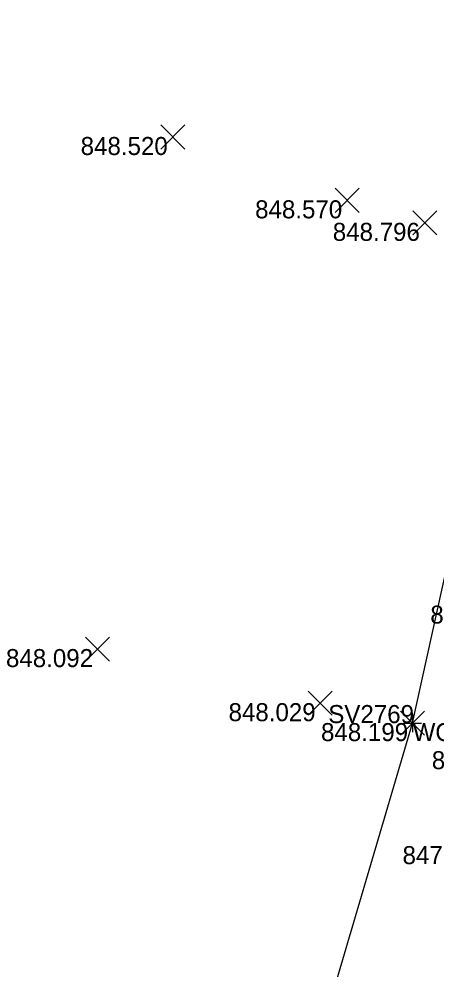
# Model space of a CAD drawing. Extents: x 2228183 to 2230895, y 679226 to 682223.
# Drawn here: x 2228275.5 to 2228298.7, y 680707.7 to 680760.4 of the extents above; entities that cross this region are included whole.
import ezdxf

# ---------------------------------------------------------------- set-up
doc = ezdxf.new("R2010")
doc.units = 0
for name, color, linetype in [('SC_Scratch1', 7, 'Continuous'), ('SV_P_Control_Cells_Set', 7, 'Continuous'), ('SV_X_Random_Point', 7, 'Continuous'), ('SV_X_Shot_Marker', 7, 'Continuous'), ('SV_X_Text_Comment', 7, 'Continuous'), ('VG_X_Tree_Line_Rt', 7, 'Continuous')]:
    doc.layers.add(name, color=color, linetype=linetype)

msp = doc.modelspace()

# ---------------------------------------------------------------- linework, layer by layer
at = {"layer": 'SV_X_Random_Point'}
for p, q in [((2228283.403, 680753.2), (2228284.737, 680754.535)), ((2228283.403, 680754.535), (2228284.737, 680753.2)), ((2228293.085, 680749.688), (2228294.419, 680751.023)), ((2228293.085, 680751.023), (2228294.419, 680749.688)), ((2228297.385, 680748.44), (2228298.719, 680749.775)), ((2228297.385, 680749.775), (2228298.719, 680748.44)), ((2228279.217, 680724.801), (2228280.551, 680726.136)), ((2228279.217, 680726.136), (2228280.551, 680724.801)), ((2228291.581, 680721.801), (2228292.915, 680723.136)), ((2228291.581, 680723.136), (2228292.915, 680721.801)), ((2228296.713, 680720.696), (2228298.047, 680722.031)), ((2228296.713, 680722.031), (2228298.047, 680720.696))]:
    msp.add_line(p, q, dxfattribs=at)
at = {"layer": 'SV_X_Shot_Marker'}
for p, q in [((2228297.38, 680721.863), (2228297.38, 680720.863)), ((2228296.88, 680721.363), (2228297.88, 680721.363)), ((2228297.38, 680721.363), (2228297.38, 680721.363))]:
    msp.add_line(p, q, dxfattribs=at)
at = {"layer": 'VG_X_Tree_Line_Rt'}
msp.add_lwpolyline([(2228242.224, 680398.608), (2228254.757, 680454.617), (2228285.377, 680608.953), (2228295.459, 680686.843), (2228290.96, 680699.609), (2228297.38, 680721.363), (2228313.146, 680792.869)], dxfattribs=at)

# ---------------------------------------------------------------- texts
at = {"layer": 'SC_Scratch1'}
for s, p in [('848.520', (2228278.956, 680752.867)), ('848.570', (2228288.638, 680749.355)), ('848.796', (2228292.948, 680748.107)), ('848.499', (2228298.362, 680726.882)), ('848.092', (2228274.811, 680724.468)), ('848.029', (2228287.164, 680721.468)), ('848.199', (2228292.296, 680720.363)), ('848.199', (2228292.296, 680720.363)), ('848.160', (2228298.445, 680718.805)), ('847.992', (2228296.82, 680713.541))]:
    msp.add_text(s, height=1, dxfattribs=at).set_placement(p)
at = {"layer": 'SV_P_Control_Cells_Set'}
msp.add_text('SV2769', height=1, dxfattribs=at).set_placement((2228292.698, 680721.363))
at = {"layer": 'SV_X_Text_Comment'}
msp.add_text('WOODSL', height=1, dxfattribs=at).set_placement((2228297.38, 680720.363))

doc.saveas('drawing.dxf')
